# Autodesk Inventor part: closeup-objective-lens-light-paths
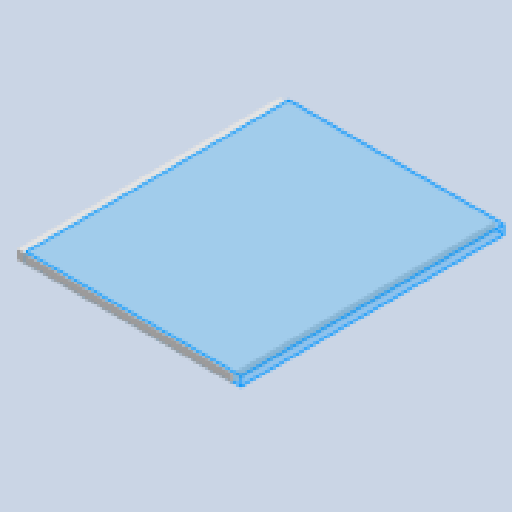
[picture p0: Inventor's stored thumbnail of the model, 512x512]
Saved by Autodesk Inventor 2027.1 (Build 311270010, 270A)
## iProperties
Created: 2026-08
Part Number: closeup-objective-lens-light-paths
Material: Generic
Document SubType Name: Modeling
Designer: dunge
Density: 1 g/cm^3
Appearance: Default
Author: dunge
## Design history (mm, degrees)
sketch "Sketch1"
  geometry: L1 (6.288, -0.362)-(6.288, 5.988) reference; L2 (-9.105, 2.813)-(98.642, 2.813) reference; L3 (6.288, 5.988)-(1.753, 2.813); L4 (1.753, 2.813)-(-2.781, 5.988); L5 (6.288, 5.988)-(-2.781, 5.988); L6 (1.753, 2.813)-(-34.523, 28.214); L7 (-34.523, 28.214)-(-34.523, 2.813); L8 (-9.105, 2.813)-(-34.523, 2.813); 3 further points
  constraints: 14 end point, 2 horizontal, 2 point on line, 1 collinear, 1 equal length, 1 midpoint, 1 perpendicular, 1 vertical, 2 other
  dimensions: "d0" = 55 deg angle of L1 L3
revolve "Revolution1" sketch "Sketch1" stored, may be unused: angle "d1" = 90 deg
sketch "Sketch2"
  geometry: L1 (31.76, -2.813)-(-6.288, -2.813); L2 (-6.288, -2.813)-(-6.288, 0.362); L3 (-6.288, 0.362)-(31.76, 10.557); L4 (31.76, 10.557)-(31.76, -2.813); L5 (9.105, 0.178)-(-98.642, 0.178) reference; L6 (9.105, -2.813)-(-98.642, -2.813) reference; L7 (-6.288, 0.362)-(-6.288, -5.988) reference; 1 further point
  constraints: 12 end point, 3 horizontal, 1 midpoint, 1 parallel, 1 perpendicular, 4 other
  dimensions: "d2" = 105 deg angle of L2 L3
revolve "Revolution2" sketch "Sketch2" stored, may be unused: angle "d3" = 360 deg
workplane "Work Plane1"
sketch "Sketch4"
  geometry: L1 (330.701, -367.832)-(-282.115, -367.832); L2 (-282.115, -367.832)-(-282.115, 381.165); L3 (-282.115, 381.165)-(330.701, 381.165); L4 (330.701, 381.165)-(330.701, -367.832); 1 further point
  constraints: 8 end point, 2 parallel, 1 horizontal, 1 perpendicular
extrude "Extrusion2" new body sketch "Sketch4" distance "d7" = 25.4; taper "d8" = 0 deg
node "red light"
node "Finishes"
node "Reference1"
node "blue light"
node "Reference3"
node "white backing"
node "Finish1" dims "Finish1_Area" = 45899.7332
other parameters: "d6" = 50.8
